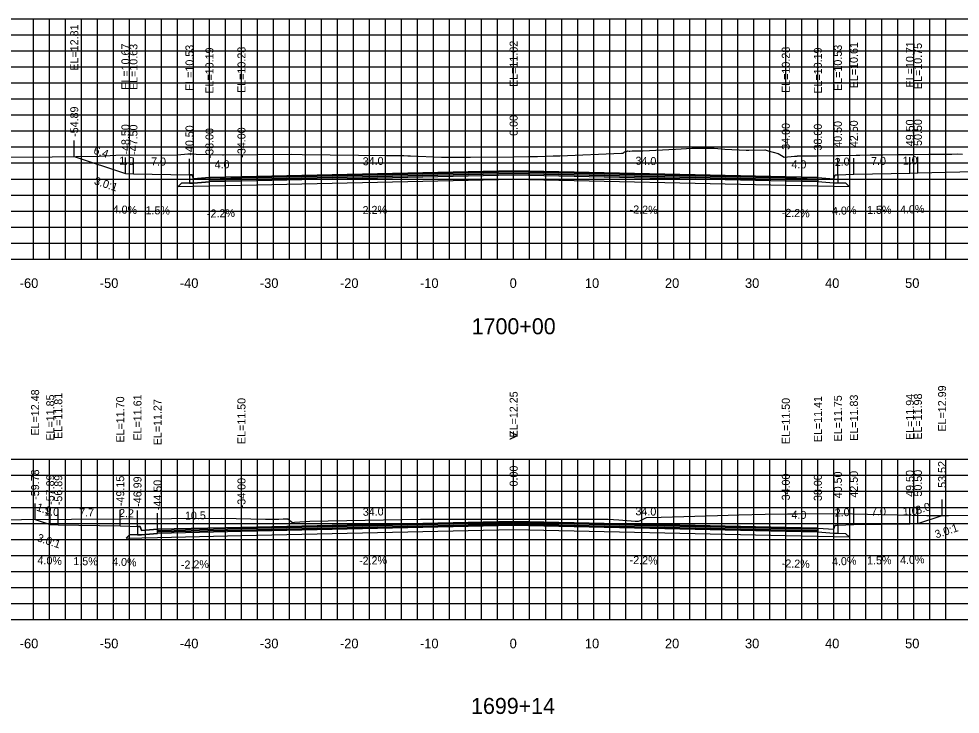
# Model space of a CAD drawing. Extents: x 1797789 to 1803805, y 249066 to 250293.
# Drawn here: x 1802229.2 to 1802346.8, y 250087.6 to 250174.4 of the extents above; entities that cross this region are included whole.
import ezdxf

# ---------------------------------------------------------------- set-up
doc = ezdxf.new("R2010")
doc.units = 0
for name, color, linetype in [('1', 7, 'Continuous'), ('10', 7, 'Continuous'), ('3', 7, 'Continuous'), ('4', 7, 'Continuous'), ('60', 7, 'Continuous'), ('BASE', 7, 'Continuous'), ('CL-CNST', 7, 'Continuous'), ('Level 62', 7, 'Continuous'), ('LOWER BINDER', 7, 'Continuous'), ('M-ROADS', 7, 'Continuous'), ('UPPER BINDER', 7, 'Continuous'), ('WEARING', 7, 'Continuous')]:
    doc.layers.add(name, color=color, linetype=linetype)

msp = doc.modelspace()

# ---------------------------------------------------------------- linework, layer by layer
for p, q in [((1802236.11, 250157.24), (1802236.11, 250159.24)), ((1802242.5, 250155.11), (1802242.5, 250157.11)), ((1802243.5, 250155.07), (1802243.5, 250157.07)), ((1802250.5, 250154.96), (1802250.5, 250156.96)), ((1802250.5, 250154.96), (1802250.5, 250156.96)), ((1802253, 250154.62), (1802253, 250156.62)), ((1802257, 250154.71), (1802257, 250156.71)), ((1802291, 250155.46), (1802291, 250157.46)), ((1802325, 250154.71), (1802325, 250156.71)), ((1802329, 250154.62), (1802329, 250156.62)), ((1802331.5, 250154.96), (1802331.5, 250156.96)), ((1802333.5, 250155.04), (1802333.5, 250157.04)), ((1802340.5, 250155.15), (1802340.5, 250157.15)), ((1802341.5, 250155.19), (1802341.5, 250157.19)), ((1802344.52, 250112.42), (1802344.52, 250114.42)), ((1802231.22, 250111.91), (1802231.22, 250113.91)), ((1802233.11, 250111.29), (1802233.11, 250113.29)), ((1802234.11, 250111.25), (1802234.11, 250113.25)), ((1802241.85, 250111.13), (1802241.85, 250113.13)), ((1802244.01, 250111.04), (1802244.01, 250113.04)), ((1802257, 250110.93), (1802257, 250112.93)), ((1802291, 250111.68), (1802291, 250113.68)), ((1802325, 250110.93), (1802325, 250112.93)), ((1802329, 250110.85), (1802329, 250112.85)), ((1802331.5, 250111.19), (1802331.5, 250113.19)), ((1802333.5, 250111.27), (1802333.5, 250113.27)), ((1802340.5, 250111.37), (1802340.5, 250113.37)), ((1802341.5, 250111.41), (1802341.5, 250113.41)), ((1802246.51, 250110.7), (1802246.51, 250112.7))]:
    msp.add_line(p, q)
for points in [[(1802253, 250154.62), (1802251, 250154.46), (1802250.83, 250154.96), (1802250.5, 250154.96), (1802250.5, 250153.93), (1802251, 250153.93), (1802253, 250154.09)], [(1802329, 250154.62), (1802331, 250154.46), (1802331.17, 250154.96), (1802331.5, 250154.96), (1802331.5, 250153.93), (1802331, 250153.93), (1802329, 250154.09)], [(1802246.51, 250110.7), (1802244.51, 250110.54), (1802244.34, 250111.04), (1802244.01, 250111.04), (1802244.01, 250110.01), (1802244.51, 250110.01), (1802246.51, 250110.17)], [(1802329, 250110.85), (1802331, 250110.69), (1802331.17, 250111.19), (1802331.5, 250111.19), (1802331.5, 250110.16), (1802331, 250110.16), (1802329, 250110.32)]]:
    msp.add_lwpolyline(points, close=True)
at = {"layer": '60'}
for p, q in [((1802141, 250144.43), (1802441, 250144.43)), ((1802231, 250144.37), (1802231, 250144.43)), ((1802241, 250144.37), (1802241, 250144.43)), ((1802251, 250144.37), (1802251, 250144.43)), ((1802261, 250144.37), (1802261, 250144.43)), ((1802271, 250144.37), (1802271, 250144.43)), ((1802281, 250144.37), (1802281, 250144.43)), ((1802291, 250144.37), (1802291, 250144.43)), ((1802301, 250144.37), (1802301, 250144.43)), ((1802311, 250144.37), (1802311, 250144.43)), ((1802321, 250144.37), (1802321, 250144.43)), ((1802331, 250144.37), (1802331, 250144.43)), ((1802341, 250144.37), (1802341, 250144.43)), ((1802141, 250099.43), (1802441, 250099.43)), ((1802231, 250099.37), (1802231, 250099.43)), ((1802241, 250099.37), (1802241, 250099.43)), ((1802251, 250099.37), (1802251, 250099.43)), ((1802261, 250099.37), (1802261, 250099.43)), ((1802271, 250099.37), (1802271, 250099.43)), ((1802281, 250099.37), (1802281, 250099.43)), ((1802291, 250099.37), (1802291, 250099.43)), ((1802301, 250099.37), (1802301, 250099.43)), ((1802311, 250099.37), (1802311, 250099.43)), ((1802321, 250099.37), (1802321, 250099.43)), ((1802331, 250099.37), (1802331, 250099.43)), ((1802341, 250099.37), (1802341, 250099.43))]:
    msp.add_line(p, q, dxfattribs=at)
at = {"layer": 'BASE'}
for points in [[(1802329, 250153.59), (1802332.9, 250153.5), (1802332.5, 250153.91), (1802331.5, 250153.93), (1802331, 250153.93), (1802329, 250154.09), (1802325, 250154.18), (1802291, 250154.93), (1802257, 250154.18), (1802253, 250154.09), (1802251, 250153.93), (1802250.5, 250153.93), (1802249.5, 250153.91), (1802249.1, 250153.5), (1802253, 250153.59), (1802257, 250153.68), (1802291, 250154.43), (1802325, 250153.68)], [(1802329, 250109.82), (1802332.9, 250109.73), (1802332.5, 250110.13), (1802331.5, 250110.16), (1802331, 250110.16), (1802329, 250110.32), (1802325, 250110.4), (1802291, 250111.15), (1802257, 250110.4), (1802246.51, 250110.17), (1802244.51, 250110.01), (1802244.01, 250110.01), (1802243.01, 250109.99), (1802242.6, 250109.59), (1802246.51, 250109.67), (1802257, 250109.9), (1802291, 250110.65), (1802325, 250109.9)]]:
    msp.add_lwpolyline(points, close=True, dxfattribs=at)
at = {"layer": 'CL-CNST'}
for points in [[(1802236.11, 250157.24), (1802242.5, 250155.11), (1802243.5, 250155.07), (1802250.5, 250154.96), (1802250.5, 250154.96), (1802250.83, 250154.96), (1802251, 250154.46), (1802253, 250154.62), (1802257, 250154.71), (1802291, 250155.46), (1802325, 250154.71), (1802329, 250154.62), (1802331, 250154.46), (1802331.17, 250154.96), (1802331.5, 250154.96), (1802333.5, 250155.04), (1802340.5, 250155.15), (1802341.5, 250155.19), (1802425.49, 250157.21)], [(1802231.22, 250111.91), (1802233.11, 250111.29), (1802234.11, 250111.25), (1802241.85, 250111.13), (1802244.01, 250111.04), (1802244.34, 250111.04), (1802244.51, 250110.54), (1802246.51, 250110.7), (1802257, 250110.93), (1802291, 250111.68), (1802325, 250110.93), (1802329, 250110.85), (1802331, 250110.69), (1802331.17, 250111.19), (1802331.5, 250111.19), (1802333.5, 250111.27), (1802340.5, 250111.37), (1802341.5, 250111.41), (1802344.52, 250112.42)]]:
    msp.add_lwpolyline(points, dxfattribs=at)
at = {"layer": 'Level 62'}
for p, q in [((1802141, 250174.43), (1802441, 250174.43)), ((1802231, 250144.43), (1802231, 250174.43)), ((1802233, 250144.43), (1802233, 250174.43)), ((1802235, 250144.43), (1802235, 250174.43)), ((1802237, 250144.43), (1802237, 250174.43)), ((1802239, 250144.43), (1802239, 250174.43)), ((1802241, 250144.43), (1802241, 250174.43)), ((1802243, 250144.43), (1802243, 250174.43)), ((1802245, 250144.43), (1802245, 250174.43)), ((1802247, 250144.43), (1802247, 250174.43)), ((1802249, 250144.43), (1802249, 250174.43)), ((1802251, 250144.43), (1802251, 250174.43)), ((1802253, 250144.43), (1802253, 250174.43)), ((1802255, 250144.43), (1802255, 250174.43)), ((1802257, 250144.43), (1802257, 250174.43)), ((1802259, 250144.43), (1802259, 250174.43)), ((1802261, 250144.43), (1802261, 250174.43)), ((1802263, 250144.43), (1802263, 250174.43)), ((1802265, 250144.43), (1802265, 250174.43)), ((1802267, 250144.43), (1802267, 250174.43)), ((1802269, 250144.43), (1802269, 250174.43)), ((1802271, 250144.43), (1802271, 250174.43)), ((1802273, 250144.43), (1802273, 250174.43)), ((1802275, 250144.43), (1802275, 250174.43)), ((1802277, 250144.43), (1802277, 250174.43)), ((1802279, 250144.43), (1802279, 250174.43)), ((1802281, 250144.43), (1802281, 250174.43)), ((1802283, 250144.43), (1802283, 250174.43)), ((1802285, 250144.43), (1802285, 250174.43)), ((1802287, 250144.43), (1802287, 250174.43)), ((1802289, 250144.43), (1802289, 250174.43)), ((1802291, 250144.43), (1802291, 250174.43)), ((1802293, 250144.43), (1802293, 250174.43)), ((1802295, 250144.43), (1802295, 250174.43)), ((1802297, 250144.43), (1802297, 250174.43)), ((1802299, 250144.43), (1802299, 250174.43)), ((1802301, 250144.43), (1802301, 250174.43)), ((1802303, 250144.43), (1802303, 250174.43)), ((1802305, 250144.43), (1802305, 250174.43)), ((1802307, 250144.43), (1802307, 250174.43)), ((1802309, 250144.43), (1802309, 250174.43)), ((1802311, 250144.43), (1802311, 250174.43)), ((1802313, 250144.43), (1802313, 250174.43)), ((1802315, 250144.43), (1802315, 250174.43)), ((1802317, 250144.43), (1802317, 250174.43)), ((1802319, 250144.43), (1802319, 250174.43)), ((1802321, 250144.43), (1802321, 250174.43)), ((1802323, 250144.43), (1802323, 250174.43)), ((1802325, 250144.43), (1802325, 250174.43)), ((1802327, 250144.43), (1802327, 250174.43)), ((1802329, 250144.43), (1802329, 250174.43)), ((1802331, 250144.43), (1802331, 250174.43)), ((1802333, 250144.43), (1802333, 250174.43)), ((1802335, 250144.43), (1802335, 250174.43)), ((1802337, 250144.43), (1802337, 250174.43)), ((1802339, 250144.43), (1802339, 250174.43)), ((1802341, 250144.43), (1802341, 250174.43)), ((1802343, 250144.43), (1802343, 250174.43)), ((1802345, 250144.43), (1802345, 250174.43)), ((1802141, 250172.43), (1802441, 250172.43)), ((1802141, 250170.43), (1802441, 250170.43)), ((1802141, 250168.43), (1802441, 250168.43)), ((1802141, 250166.43), (1802441, 250166.43)), ((1802141, 250164.43), (1802441, 250164.43)), ((1802141, 250162.43), (1802441, 250162.43)), ((1802141, 250160.43), (1802441, 250160.43)), ((1802141, 250158.43), (1802441, 250158.43)), ((1802141, 250156.43), (1802441, 250156.43)), ((1802141, 250154.43), (1802441, 250154.43)), ((1802141, 250152.43), (1802441, 250152.43)), ((1802141, 250150.43), (1802441, 250150.43)), ((1802141, 250148.43), (1802441, 250148.43)), ((1802141, 250146.43), (1802441, 250146.43)), ((1802141, 250144.43), (1802441, 250144.43)), ((1802141, 250119.43), (1802441, 250119.43)), ((1802231, 250099.43), (1802231, 250119.43)), ((1802233, 250099.43), (1802233, 250119.43)), ((1802235, 250099.43), (1802235, 250119.43)), ((1802237, 250099.43), (1802237, 250119.43)), ((1802239, 250099.43), (1802239, 250119.43)), ((1802241, 250099.43), (1802241, 250119.43)), ((1802243, 250099.43), (1802243, 250119.43)), ((1802245, 250099.43), (1802245, 250119.43)), ((1802247, 250099.43), (1802247, 250119.43)), ((1802249, 250099.43), (1802249, 250119.43)), ((1802251, 250099.43), (1802251, 250119.43)), ((1802253, 250099.43), (1802253, 250119.43)), ((1802255, 250099.43), (1802255, 250119.43)), ((1802257, 250099.43), (1802257, 250119.43)), ((1802259, 250099.43), (1802259, 250119.43)), ((1802261, 250099.43), (1802261, 250119.43)), ((1802263, 250099.43), (1802263, 250119.43)), ((1802265, 250099.43), (1802265, 250119.43)), ((1802267, 250099.43), (1802267, 250119.43)), ((1802269, 250099.43), (1802269, 250119.43)), ((1802271, 250099.43), (1802271, 250119.43)), ((1802273, 250099.43), (1802273, 250119.43)), ((1802275, 250099.43), (1802275, 250119.43)), ((1802277, 250099.43), (1802277, 250119.43)), ((1802279, 250099.43), (1802279, 250119.43)), ((1802281, 250099.43), (1802281, 250119.43)), ((1802283, 250099.43), (1802283, 250119.43)), ((1802285, 250099.43), (1802285, 250119.43)), ((1802287, 250099.43), (1802287, 250119.43)), ((1802289, 250099.43), (1802289, 250119.43)), ((1802291, 250099.43), (1802291, 250119.43)), ((1802293, 250099.43), (1802293, 250119.43)), ((1802295, 250099.43), (1802295, 250119.43)), ((1802297, 250099.43), (1802297, 250119.43)), ((1802299, 250099.43), (1802299, 250119.43)), ((1802301, 250099.43), (1802301, 250119.43)), ((1802303, 250099.43), (1802303, 250119.43)), ((1802305, 250099.43), (1802305, 250119.43)), ((1802307, 250099.43), (1802307, 250119.43)), ((1802309, 250099.43), (1802309, 250119.43)), ((1802311, 250099.43), (1802311, 250119.43)), ((1802313, 250099.43), (1802313, 250119.43)), ((1802315, 250099.43), (1802315, 250119.43)), ((1802317, 250099.43), (1802317, 250119.43)), ((1802319, 250099.43), (1802319, 250119.43)), ((1802321, 250099.43), (1802321, 250119.43)), ((1802323, 250099.43), (1802323, 250119.43)), ((1802325, 250099.43), (1802325, 250119.43)), ((1802327, 250099.43), (1802327, 250119.43)), ((1802329, 250099.43), (1802329, 250119.43)), ((1802331, 250099.43), (1802331, 250119.43)), ((1802333, 250099.43), (1802333, 250119.43)), ((1802335, 250099.43), (1802335, 250119.43)), ((1802337, 250099.43), (1802337, 250119.43)), ((1802339, 250099.43), (1802339, 250119.43)), ((1802341, 250099.43), (1802341, 250119.43)), ((1802343, 250099.43), (1802343, 250119.43)), ((1802345, 250099.43), (1802345, 250119.43)), ((1802141, 250117.43), (1802441, 250117.43)), ((1802141, 250115.43), (1802441, 250115.43)), ((1802141, 250113.43), (1802441, 250113.43)), ((1802141, 250111.43), (1802441, 250111.43)), ((1802141, 250109.43), (1802441, 250109.43)), ((1802141, 250107.43), (1802441, 250107.43)), ((1802141, 250105.43), (1802441, 250105.43)), ((1802141, 250103.43), (1802441, 250103.43)), ((1802141, 250101.43), (1802441, 250101.43)), ((1802141, 250099.43), (1802441, 250099.43))]:
    msp.add_line(p, q, dxfattribs=at)
at = {"layer": 'LOWER BINDER'}
for points in [[(1802253, 250154.09), (1802253, 250154.28), (1802257, 250154.37), (1802291, 250155.12), (1802325, 250154.37), (1802329, 250154.28), (1802329, 250154.09), (1802325, 250154.18), (1802291, 250154.93), (1802257, 250154.18)], [(1802246.51, 250110.17), (1802246.51, 250110.36), (1802257, 250110.59), (1802291, 250111.34), (1802325, 250110.59), (1802329, 250110.51), (1802329, 250110.32), (1802325, 250110.4), (1802291, 250111.15), (1802257, 250110.4)]]:
    msp.add_lwpolyline(points, close=True, dxfattribs=at)
at = {"layer": 'M-ROADS'}
for points in [[(1802225.7, 250157.14), (1802233.36, 250157.19), (1802239.21, 250157.29), (1802241.29, 250157.41), (1802249.01, 250157.45), (1802250.3, 250157.56), (1802250.51, 250157.56), (1802250.74, 250157.56), (1802250.89, 250157.56), (1802251.32, 250157.55), (1802254.62, 250157.45), (1802254.75, 250157.45), (1802263.26, 250157.53), (1802264.57, 250157.49), (1802275.12, 250157.38), (1802275.21, 250157.37), (1802275.46, 250157.35), (1802277.11, 250157.36), (1802277.26, 250157.36), (1802277.27, 250157.36), (1802277.78, 250157.34), (1802277.87, 250157.34), (1802277.97, 250157.33), (1802278.01, 250157.33), (1802278.1, 250157.33), (1802281.98, 250157.16), (1802284.52, 250157.15), (1802284.74, 250157.15), (1802285.6, 250157.15), (1802291.02, 250157.2), (1802292.84, 250157.23), (1802292.93, 250157.23), (1802293.18, 250157.23), (1802293.2, 250157.23), (1802293.34, 250157.24), (1802293.46, 250157.24), (1802293.48, 250157.24), (1802293.77, 250157.25), (1802293.8, 250157.25), (1802293.97, 250157.25), (1802295.94, 250157.31), (1802296.5, 250157.32), (1802296.76, 250157.33), (1802304.48, 250157.65), (1802304.68, 250157.65), (1802304.84, 250157.83), (1802304.9, 250157.82), (1802305.02, 250157.86), (1802305.08, 250157.87), (1802305.28, 250157.93), (1802305.45, 250157.91), (1802305.52, 250157.9), (1802305.8, 250157.96), (1802306.04, 250157.94), (1802306.14, 250157.93), (1802306.57, 250157.94), (1802306.94, 250157.93), (1802307.13, 250157.93), (1802311.2, 250158.17), (1802311.93, 250158.21), (1802313.26, 250158.29), (1802315.49, 250158.3), (1802315.61, 250158.3), (1802316.06, 250158.29), (1802317.38, 250158.14), (1802320.06, 250158.02), (1802320.39, 250158.02), (1802322.37, 250158.07), (1802322.41, 250158.07), (1802322.79, 250157.96), (1802324.03, 250157.6), (1802324.44, 250157.36), (1802324.79, 250157.14), (1802326.07, 250157.27), (1802326.17, 250157.28), (1802326.29, 250157.29), (1802326.43, 250157.3), (1802326.47, 250157.31), (1802327.28, 250157.32), (1802328.48, 250157.34), (1802328.82, 250157.34), (1802331.35, 250157.38), (1802331.79, 250157.38), (1802333.77, 250157.41), (1802334.23, 250157.42), (1802335.55, 250157.43), (1802337.11, 250157.46), (1802338.92, 250157.48), (1802339.98, 250157.5), (1802340.11, 250157.5), (1802340.9, 250157.51), (1802342.86, 250157.53), (1802343.3, 250157.53), (1802345.73, 250157.55), (1802346.47, 250157.56), (1802347.09, 250157.55)], [(1802210.72, 250111.77), (1802254.5, 250112.08), (1802260, 250111.95), (1802261.1, 250111.97), (1802261.65, 250111.97), (1802262.21, 250111.98), (1802262.34, 250111.98), (1802262.81, 250111.98), (1802263.2, 250111.67), (1802263.36, 250111.53), (1802263.64, 250111.56), (1802264.95, 250111.68), (1802265.52, 250111.69), (1802279.35, 250111.97), (1802284.79, 250111.96), (1802287.72, 250111.95), (1802290.27, 250111.95), (1802297.36, 250111.95), (1802300.54, 250111.94), (1802302.79, 250111.94), (1802304.14, 250111.85), (1802306.18, 250111.72), (1802306.36, 250111.7), (1802306.6, 250111.69), (1802306.83, 250111.8), (1802307.59, 250112.17), (1802309.41, 250112.22), (1802316.48, 250112.42), (1802319.11, 250112.49), (1802322.4, 250112.56), (1802325.19, 250112.61), (1802326.46, 250112.62), (1802331.49, 250112.67), (1802342.62, 250112.41), (1802345.31, 250112.42), (1802357.33, 250112.57)]]:
    msp.add_lwpolyline(points, dxfattribs=at)
at = {"layer": 'UPPER BINDER'}
for points in [[(1802291, 250155.12), (1802257, 250154.37), (1802253, 250154.28), (1802253, 250154.47), (1802257, 250154.56), (1802291, 250155.31), (1802325, 250154.56), (1802329, 250154.47), (1802329, 250154.09), (1802329, 250154.28), (1802325, 250154.37)], [(1802291, 250111.34), (1802257, 250110.59), (1802246.51, 250110.36), (1802246.51, 250110.55), (1802257, 250110.78), (1802291, 250111.53), (1802325, 250110.78), (1802329, 250110.7), (1802329, 250110.32), (1802329, 250110.51), (1802325, 250110.59)]]:
    msp.add_lwpolyline(points, close=True, dxfattribs=at)
at = {"layer": 'WEARING'}
for points in [[(1802329, 250154.47), (1802329, 250154.62), (1802325, 250154.71), (1802291, 250155.46), (1802257, 250154.71), (1802253, 250154.62), (1802253, 250154.47), (1802257, 250154.56), (1802291, 250155.31), (1802325, 250154.56)], [(1802329, 250110.7), (1802329, 250110.85), (1802325, 250110.93), (1802291, 250111.68), (1802257, 250110.93), (1802246.51, 250110.7), (1802246.51, 250110.55), (1802257, 250110.78), (1802291, 250111.53), (1802325, 250110.78)]]:
    msp.add_lwpolyline(points, close=True, dxfattribs=at)

# ---------------------------------------------------------------- texts
for rotation, p in [(341.5651, (1802238.51, 250153.8)), (18.4349, (1802343.8, 250109.54)), (341.5651, (1802231.38, 250109.23))]:
    msp.add_text('3.0:1', height=1, rotation=rotation).set_placement(p)
at = {"layer": '1'}
for s, p in [('1700+00', (1802285.76, 250135.04)), ('1699+14', (1802285.68, 250087.63))]:
    msp.add_text(s, height=2, dxfattribs=at).set_placement(p)
at = {"layer": '10'}
for s, p in [('-60', (1802229.3, 250140.83)), ('-50', (1802239.3, 250140.83)), ('-40', (1802249.3, 250140.83)), ('-30', (1802259.3, 250140.83)), ('-20', (1802269.3, 250140.83)), ('-10', (1802279.3, 250140.83)), ('0', (1802290.5, 250140.83)), ('10', (1802299.9, 250140.83)), ('20', (1802309.9, 250140.83)), ('30', (1802319.9, 250140.83)), ('40', (1802329.9, 250140.83)), ('50', (1802339.9, 250140.83)), ('-60', (1802229.3, 250095.83)), ('-50', (1802239.3, 250095.83)), ('-40', (1802249.3, 250095.83)), ('-30', (1802259.3, 250095.83)), ('-20', (1802269.3, 250095.83)), ('-10', (1802279.3, 250095.83)), ('0', (1802290.5, 250095.83)), ('10', (1802299.9, 250095.83)), ('20', (1802309.9, 250095.83)), ('30', (1802319.9, 250095.83)), ('40', (1802329.9, 250095.83)), ('50', (1802339.9, 250095.83))]:
    msp.add_text(s, height=1.2, dxfattribs=at).set_placement(p)
at = {"layer": '3'}
for s, p in [('EL=12.81', (1802236.61, 250167.96)), ('EL=11.02', (1802291.5, 250165.93)), ('EL=10.67', (1802243, 250165.58)), ('EL=10.63', (1802244, 250165.54)), ('EL=10.53', (1802251, 250165.43)), ('EL=10.53', (1802251, 250165.43)), ('EL=10.19', (1802253.5, 250165.09)), ('EL=10.28', (1802257.5, 250165.18)), ('EL=10.28', (1802325.5, 250165.18)), ('EL=10.19', (1802329.5, 250165.09)), ('EL=10.53', (1802332, 250165.43)), ('EL=10.61', (1802334, 250165.76)), ('EL=10.71', (1802341, 250165.87)), ('EL=10.75', (1802342, 250165.66)), ('-54.89', (1802236.61, 250159.69)), ('0.00', (1802291.5, 250159.82)), ('-48.50', (1802243, 250157.48)), ('-47.50', (1802244, 250157.44)), ('-40.50', (1802251, 250157.34)), ('-40.50', (1802251, 250157.34)), ('34.00', (1802325.5, 250158.08)), ('38.00', (1802329.5, 250157.99)), ('40.50', (1802332, 250158.33)), ('42.50', (1802334, 250158.41)), ('49.50', (1802341, 250158.52)), ('50.50', (1802342, 250158.56)), ('-38.00', (1802253.5, 250157)), ('-34.00', (1802257.5, 250157.09)), ('EL=12.48', (1802231.72, 250122.39)), ('EL=12.99', (1802345.02, 250122.89)), ('EL=11.85', (1802233.61, 250121.76)), ('EL=11.81', (1802234.61, 250121.97)), ('EL=11.70', (1802242.35, 250121.52)), ('EL=11.61', (1802244.51, 250121.77)), ('EL=11.50', (1802257.5, 250121.33)), ('EL=12.25', (1802291.5, 250122.15)), ('EL=11.50', (1802325.5, 250121.33)), ('EL=11.41', (1802329.5, 250121.57)), ('EL=11.75', (1802332, 250121.66)), ('EL=11.83', (1802334, 250121.74)), ('EL=11.94', (1802341, 250121.84)), ('EL=11.98', (1802342, 250121.88)), ('EL=11.27', (1802247.01, 250121.18)), ('53.52', (1802345.02, 250115.87)), ('-59.78', (1802231.72, 250114.37)), ('0.00', (1802291.5, 250116.04)), ('34.00', (1802325.5, 250114.3)), ('38.00', (1802329.5, 250114.22)), ('40.50', (1802332, 250114.56)), ('42.50', (1802334, 250114.64)), ('49.50', (1802341, 250114.74)), ('50.50', (1802342, 250114.78)), ('-57.89', (1802233.61, 250113.74)), ('-56.89', (1802234.61, 250113.7)), ('-49.15', (1802242.35, 250113.59)), ('-46.99', (1802244.51, 250113.5)), ('-44.50', (1802247.01, 250113.08)), ('-34.00', (1802257.5, 250113.31))]:
    msp.add_text(s, height=1, rotation=90, dxfattribs=at).set_placement(p)
at = {"layer": '4'}
for s, rotation, p in [('6.4', 341.5651, (1802238.43, 250157.62)), ('1.0', 357.7094, (1802241.72, 250156.24)), ('7.0', 359.1406, (1802245.7, 250156.13)), ('4.0', 1.2603, (1802253.65, 250155.74)), ('34.0', 1.2603, (1802272.16, 250156.14)), ('34.0', 358.7397, (1802306.21, 250156.22)), ('4.0', 358.7397, (1802325.7, 250155.79)), ('2.0', 2.2906, (1802331.13, 250156.05)), ('7.0', 0.8594, (1802335.66, 250156.17)), ('1.0', 2.2906, (1802339.63, 250156.21)), ('4.0%', 357.7094, (1802240.89, 250150.17)), ('1.5%', 359.1406, (1802245.01, 250150.04)), ('-2.2%', 1.2603, (1802252.7, 250149.61)), ('-2.2%', 1.2603, (1802271.7, 250150.03)), ('-2.2%', 358.7397, (1802305.48, 250150.14)), ('-2.2%', 358.7397, (1802324.48, 250149.72)), ('4.0%', 2.2906, (1802330.79, 250149.93)), ('1.5%', 0.8594, (1802335.16, 250150.06)), ('4.0%', 2.2906, (1802339.29, 250150.09)), ('3.0', 18.4349, (1802341.41, 250112.54)), ('1.9', 341.5651, (1802231.3, 250113.05)), ('1.0', 357.7094, (1802232.33, 250112.42)), ('7.7', 359.1406, (1802236.71, 250112.31)), ('2.2', 357.7094, (1802241.69, 250112.24)), ('10.5', 1.2603, (1802249.95, 250111.88)), ('34.0', 1.2603, (1802272.16, 250112.37)), ('34.0', 358.7397, (1802306.21, 250112.45)), ('4.0', 358.7397, (1802325.7, 250112.02)), ('2.0', 2.2906, (1802331.13, 250112.27)), ('7.0', 0.8594, (1802335.66, 250112.4)), ('1.0', 2.2906, (1802339.63, 250112.44)), ('4.0%', 357.7094, (1802231.5, 250106.35)), ('1.5%', 359.1406, (1802235.99, 250106.22)), ('4.0%', 357.7094, (1802240.82, 250106.17)), ('-2.2%', 1.2603, (1802271.7, 250106.26)), ('-2.2%', 358.7397, (1802305.48, 250106.36)), ('-2.2%', 358.7397, (1802324.48, 250105.94)), ('4.0%', 2.2906, (1802330.79, 250106.15)), ('1.5%', 0.8594, (1802335.16, 250106.29)), ('4.0%', 2.2906, (1802339.29, 250106.32)), ('-2.2%', 1.2603, (1802249.45, 250105.77))]:
    msp.add_text(s, height=1, rotation=rotation, dxfattribs=at).set_placement(p)
at = {"layer": '60'}
msp.add_text('>', height=1.5, dxfattribs=at).set_placement((1802290.39, 250121.68))

doc.saveas('drawing.dxf')
